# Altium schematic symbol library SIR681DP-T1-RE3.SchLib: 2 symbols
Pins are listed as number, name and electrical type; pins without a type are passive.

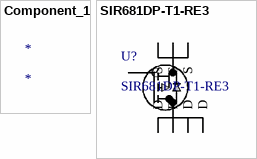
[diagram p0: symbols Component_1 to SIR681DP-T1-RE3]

## Component_1
designator *

## SIR681DP-T1-RE3
designator U?
No Description Available; Mfr_Name: Vishay
footprint MOSFET_DP-T1-RE3_VIS
pins: 1 S, 2 S, 3 S, 4 G, 5 D, 6 D, 7 D, 8 D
